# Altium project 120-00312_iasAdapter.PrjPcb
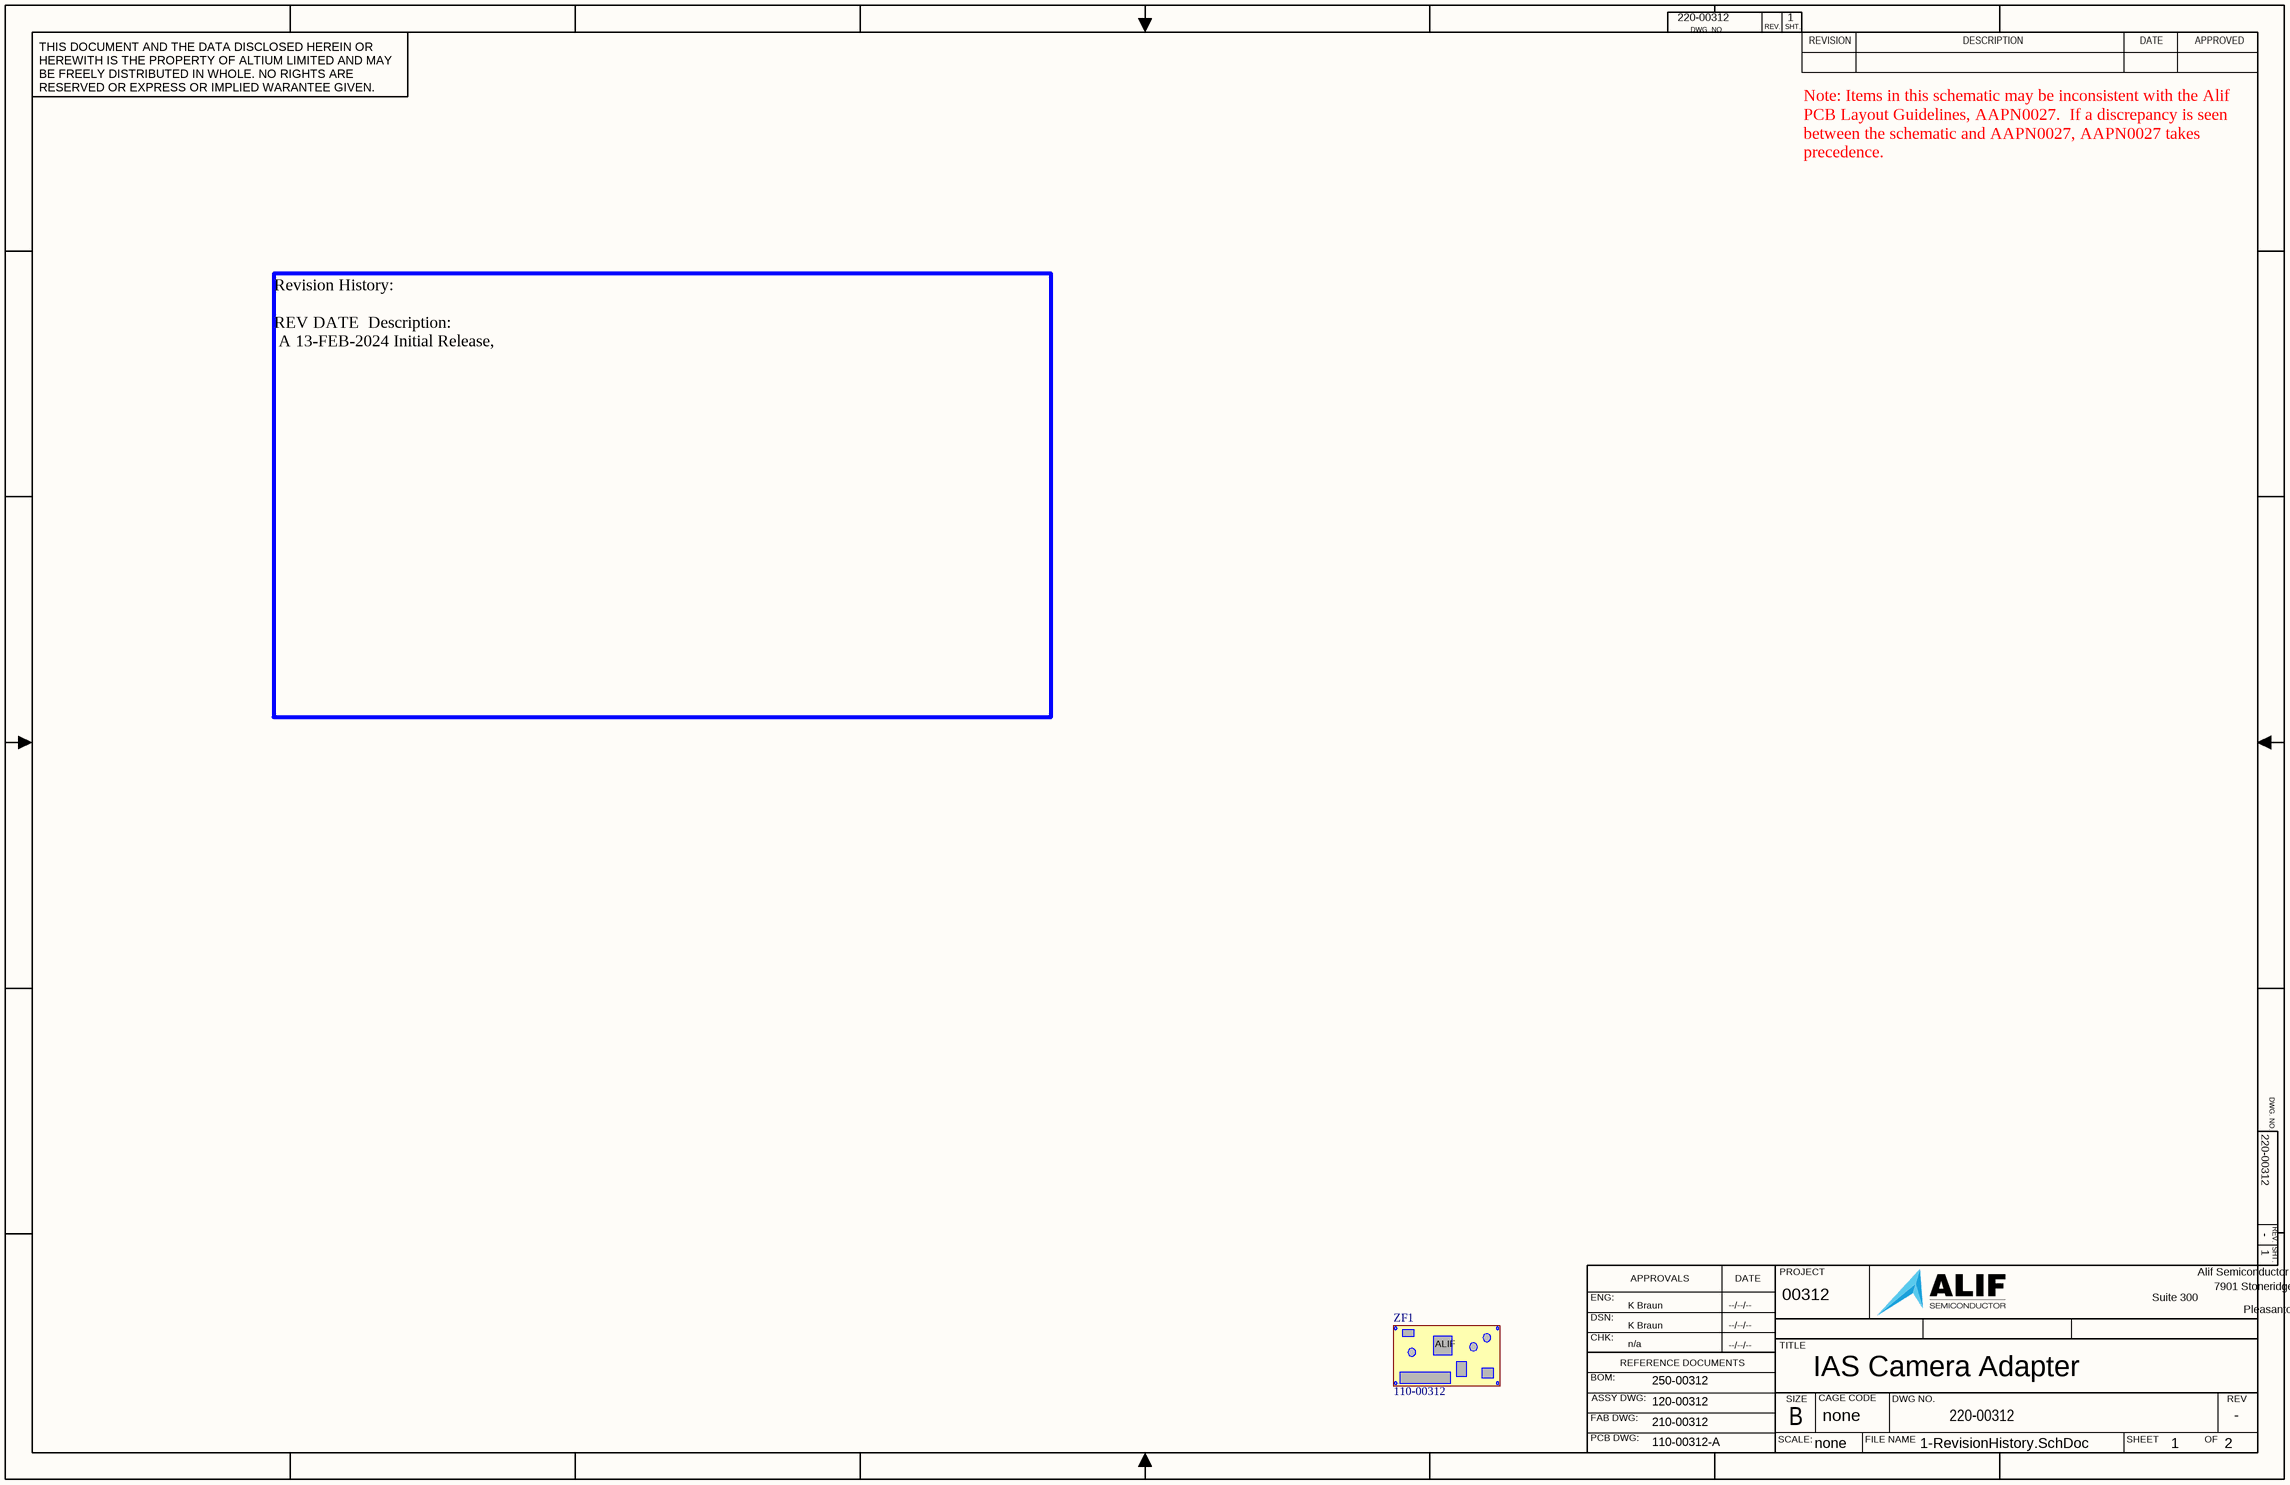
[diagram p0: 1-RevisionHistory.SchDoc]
ASSY_DWG_NO: 120-00312-A; CAGE_CODE: none; CheckedBy: n/a; CHK_APP_DATE: 02/13/24; DOC_NO_ASSY_DWG: 120-00312; DOC_NO_BOM: 250-00312; DOC_NO_FAB_DWG: 210-00312; DOC_NO_SCH_DWG: 220-00312; DOC_REV: A; DrawnBy: K Braun; DSN_APP_DATE: 02/13/24; ENG_APP_DATE: 02/13/24; Engineer: K Braun; Fab_DWG_NO: 110-00312; Name-Company: ALIF SEMICONDUCTOR; No-Fab: 110-00312; No-Rev: A; PCB_DWG_NO: 110-00312-A; PROJECT: 00312; Revision: A; SheetTotal: 2; title: IAS Camera Adapter
2 sheets, 13 parts. Net scope: flat (ports and power ports of the same name join across sheets).
Board file: 120-00312-A_iasAdapter.PcbDoc
Sheets:
  1-RevisionHistory.SchDoc
  2-Adapter.SchDoc

## Sheet 1-RevisionHistory.SchDoc: IAS Camera Adapter
size 431 x 279 mm; Organization: ORGANIZATION; Address1: ADDRESS 1; Address2: ADDRESS 2; Address3: ADDRESS 3; Address4: ADDRESS 4; DocumentNumber: 1; Revision: -; SheetNumber: 1; SheetTotal: 2; ENG_APP_DATE: --/--/--; DSN_APP_DATE: --/--/--; CHK_APP_DATE: --/--/--

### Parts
ZF1  110-00312  (mechanical)

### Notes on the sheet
- Note: Items in this schematic may be inconsistent with the Alif PCB Layout Guidelines, AAPN0027.  If a discrepancy is seen between the schematic and AAPN0027, AAPN0027 takes precedence.
- Revision History:
  REV	DATE		Description:
  A	13-FEB-2024	Initial Release,

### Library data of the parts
ZF1 = PCB_FAB: Printed Circuit Board  Fabrication; Manufacturer 1: Alif Semi; Manufacturer Part Number 1: 110-00312-A

## Sheet 2-Adapter.SchDoc: IAS Camera Adapter
size 431 x 279 mm; Organization: ORGANIZATION; Address1: ADDRESS 1; Address2: ADDRESS 2; Address3: ADDRESS 3; Address4: ADDRESS 4; Revision: -; SheetNumber: 2; SheetTotal: 2; ENG_APP_DATE: --/--/--; DSN_APP_DATE: --/--/--; CHK_APP_DATE: --/--/--
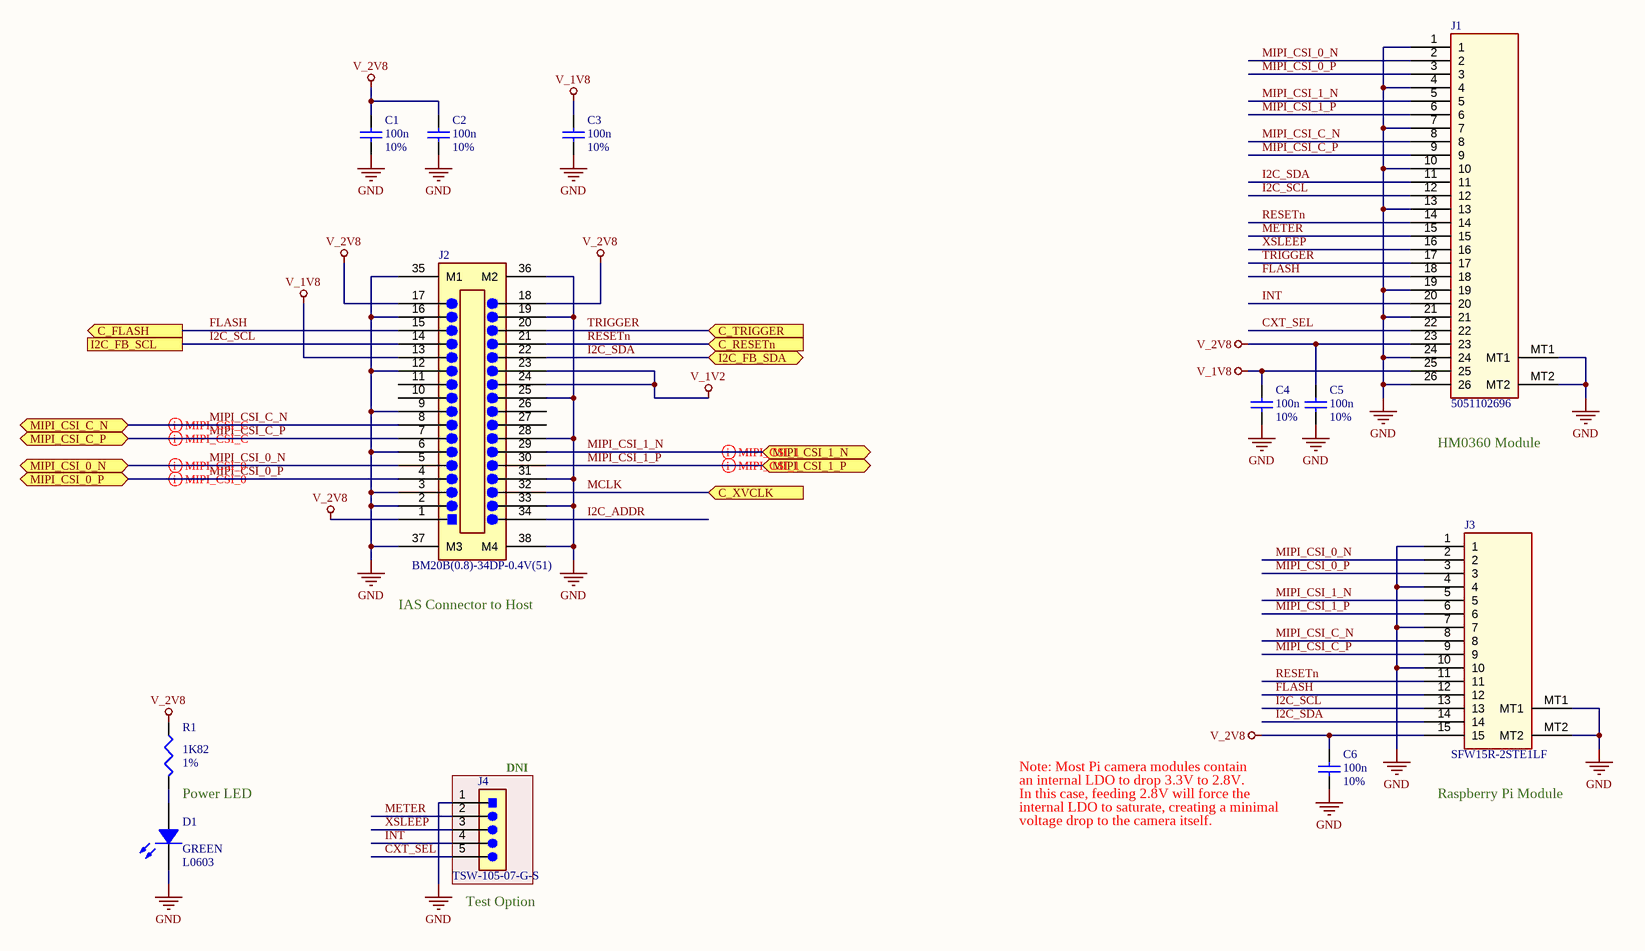
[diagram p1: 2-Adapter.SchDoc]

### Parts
C1  value 100n  Tolerance: 10%  [CAPC0402-01]  (hidden comment: Cap)
C2  value 100n  Tolerance: 10%  [CAPC0402-01]  (hidden comment: Cap)
C3  value 100n  Tolerance: 10%  [CAPC0402-01]  (hidden comment: Cap)
C4  value 100n  Tolerance: 10%  [CAPC0402-01]  (hidden comment: Cap)
C5  value 100n  Tolerance: 10%  [CAPC0402-01]  (hidden comment: Cap)
C6  value 100n  Tolerance: 10%  [CAPC0402-01]  (hidden comment: Cap)
D1  value GREEN  PackageReference: L0603  [LED_0603-GRN_AK]  (hidden comment: D LED2)
J1  5051102696  [CONN_FPC_BOT-ENT_FRONT-LOCK_0.50_26]
J2  BM20B(0.8)-34DP-0.4V(51)  [CONN_FPC_BM20B(0.8)-34DP-0.4V(51)]
J3  SFW15R-2STE1LF  [CONN_FPC_BOT-ENT_FRONT-LOCK_1.0_15]
J4  TSW-105-07-G-S  [CONN_SAMTEC_CON5_1X5_TU_TSW_dni]
R1  value 1K82  Tolerance: 1%  [RESC0402-01]  (hidden comment: Res3)

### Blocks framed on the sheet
DNI: J4

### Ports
C_FLASH (out), C_RESETn (in), C_TRIGGER (in), C_XVCLK (in), I2C_FB_SCL, I2C_FB_SDA (bidir), MIPI_CSI_0_N (bidir), MIPI_CSI_0_P (bidir), MIPI_CSI_1_N (bidir), MIPI_CSI_1_P (bidir), MIPI_CSI_C_N (bidir), MIPI_CSI_C_P (bidir)

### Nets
GND: C1.1 C2.1 C3.1 C4.1 C5.1 C6.1 D1.K J1.1 J1.4 J1.7 J1.10 J1.13 J1.19 J1.21 J1.24 J1.26 J1.MT1 J1.MT2 J2.2 J2.3 J2.6 J2.9 J2.12 J2.16 J2.19 J2.25 J2.28 J2.31 J2.33 J2.35(M1) J2.36(M2) J2.37(M3) J2.38(M4) J3.1 J3.4 J3.7 J3.10 J3.MT1 J3.MT2 J4.1
V_1V2: J2.23 J2.24
V_1V8: C3.2 C4.2 J1.25 J2.13
V_2V8: C1.2 C2.2 C5.2 C6.2 J1.23 J2.1 J2.17 J2.18 J3.15 R1.1
CXT_SEL: J1.22 J4.5
FLASH: J1.18 J2.15 J3.12 ; port C_FLASH
I2C_ADDR: J2.34
I2C_SCL: J1.12 J2.14 J3.13 ; port I2C_FB_SCL
I2C_SDA: J1.11 J2.22 J3.14 ; port I2C_FB_SDA
INT: J1.20 J4.4
MCLK: J2.32 ; port C_XVCLK
METER: J1.15 J4.2
MIPI_CSI_0_N: J1.2 J2.5 J3.2 ; port MIPI_CSI_0_N
MIPI_CSI_0_P: J1.3 J2.4 J3.3 ; port MIPI_CSI_0_P
MIPI_CSI_1_N: J1.5 J2.29 J3.5 ; port MIPI_CSI_1_N
MIPI_CSI_1_P: J1.6 J2.30 J3.6 ; port MIPI_CSI_1_P
MIPI_CSI_C_N: J1.8 J2.8 J3.8 ; port MIPI_CSI_C_N
MIPI_CSI_C_P: J1.9 J2.7 J3.9 ; port MIPI_CSI_C_P
RESETn: J1.14 J2.21 J3.11 ; port C_RESETn
TRIGGER: J1.17 J2.20 ; port C_TRIGGER
XSLEEP: J1.16 J4.3
NetD1_A: D1.A R1.2

Not connected (* = marked no-connect by the designer): J2 10 11 26 27

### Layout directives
differential pair; differential pair class MIPI_CSI_0: MIPI_CSI_0_N, MIPI_CSI_0_P
differential pair; differential pair class MIPI_CSI_1: MIPI_CSI_1_N, MIPI_CSI_1_P
differential pair; differential pair class MIPI_CSI_C: MIPI_CSI_C_N, MIPI_CSI_C_P

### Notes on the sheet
- (near J1) HM0360 Module
- (near J2) IAS Connector to Host
- (near R1) Power LED
- (near C6) Note: Most Pi camera modules contain
- (near C6) an internal LDO to drop 3.3V to 2.8V.
- (near C6) In this case, feeding 2.8V will force the
- (near C6) internal LDO to saturate, creating a minimal
- voltage drop to the camera itself.
- (near J3) Raspberry Pi Module
- (near J4) Test Option

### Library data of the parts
C1-C6 = Cap_SMT: Cap,100nF,10%,50V,X7R,0402; Manufacturer 1: TDK; Manufacturer Part Number 1: C1005X7R1H104K050BE; PCB_Footprint: CC0402
D1 = D LED2: Diode,LED,Green 573nm,300mcd @ 20mA,0603; Manufacturer 1: Wurth; Manufacturer Part Number 1: 150060VS86000
J1 = Conn_FFC_BOT_FRONT-LOCK_0.50_26pin: Conn,FlatFlex,26 pin,0.50mm,bottom-entry,front-lock,SMT; Manufacturer 1: Molex
J2 = CONN_HIROSE_BM20_FPC_34PIN_0.4MM_CAM_MODULE: Conn,FPC,34 pin,0.4mm pitch, 0,8mm height,SMT; Manufacturer 1: HiRose
J3 = Conn_FFC_BOT_SLIDE-LOCK_1.00_15pin: Conn,FlatFlex,15 pin,1.00mm,bottom-entry,slide-locking,SMT; Manufacturer 1: Amphenol; Manufacturer Part Number 1: SFW15R-1STE1LF
J4 = Hdr_M_1X5_2M54_STRT_UNSHROUD: DNI,Hdr, 0.025" SQ Post Header, Through-hole, Vertical, 2.54 mm Pitch, 5-Pin, Male; Manufacturer: Samtec; Pitch: 2.54 mm
R1 = Res3: Res,1K82,1%,100ppm,0402; Manufacturer 1: Stackpol; Manufacturer Part Number 1: RMCF0402FT1K82; Wattage: 63mW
